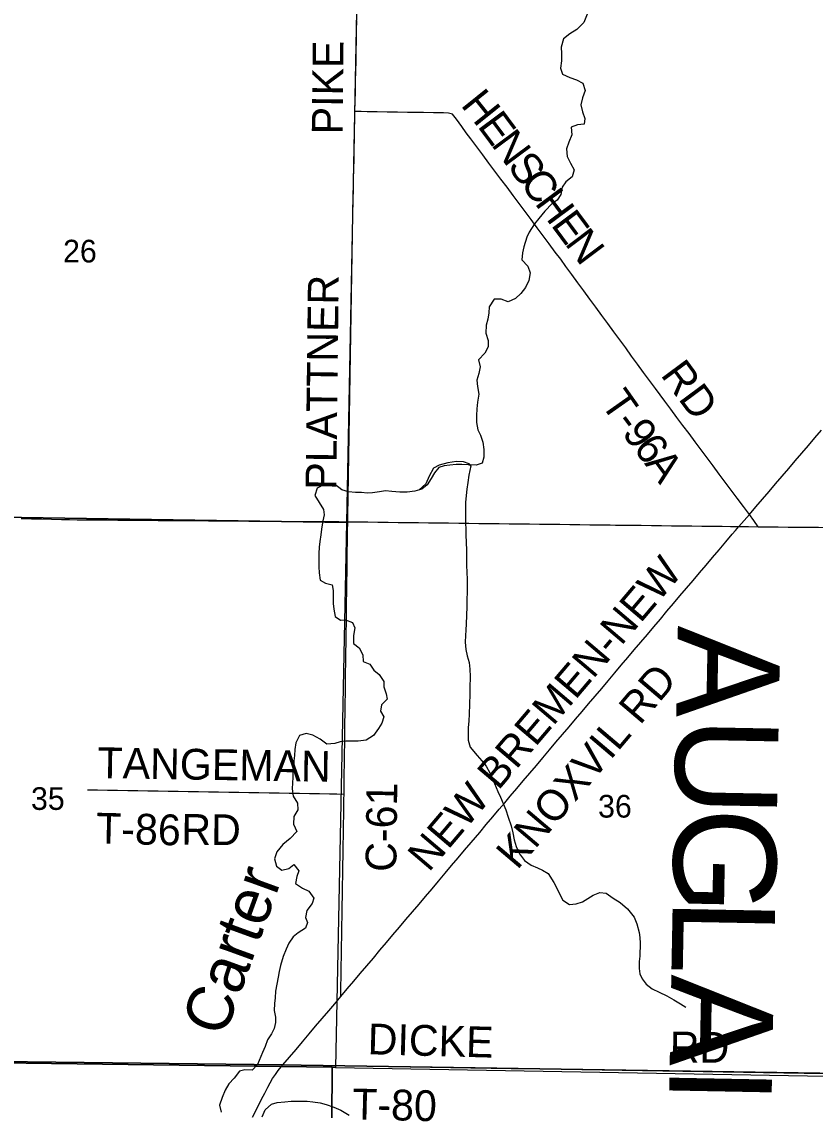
# Model space of a CAD drawing. Extents: x -11.1 to 34, y -3.9 to 22.
# Drawn here: x 5.806 to 7.271, y 18.172 to 20.181 of the extents above; entities that cross this region are included whole.
import ezdxf

# ---------------------------------------------------------------- set-up
doc = ezdxf.new("R2010")
doc.units = 0
for name, color, linetype in [('GM_X_Corporation', 7, 'Continuous'), ('GM_X_County_Road', 7, 'Continuous'), ('GM_X_County_Road_Text', 7, 'Continuous'), ('GM_X_County_Text', 7, 'Continuous'), ('GM_X_Minor_River', 7, 'Continuous'), ('GM_X_Minor_River_Text', 7, 'Continuous'), ('GM_X_Section_Text', 7, 'Continuous'), ('GM_X_Township_Road', 7, 'Continuous'), ('GM_X_Township_Road_Text', 7, 'Continuous')]:
    doc.layers.add(name, color=color, linetype=linetype)

msp = doc.modelspace()

# ---------------------------------------------------------------- linework, layer by layer
at = {"layer": 'GM_X_Corporation'}
for points in [[(7.452, 20.9), (2.1, 20.9), (2.1, 18.3243), (2.3663, 18.3195), (2.386, 18.3192), (3.3765, 18.301), (3.3885, 18.301), (4.3933, 18.2849), (4.8079, 18.2783), (5.3973, 18.2661), (6.2873, 18.2553), (6.3214, 18.2549), (6.5234, 18.2515), (7.399, 18.2383)], [(7.399, 18.2383), (6.5234, 18.2515), (6.3214, 18.2549), (6.2873, 18.2553), (5.3973, 18.2661), (4.8079, 18.2783), (4.3933, 18.2849), (3.3885, 18.301), (3.3765, 18.301), (2.386, 18.3192), (2.3663, 18.3195), (2.1, 18.3243), (2.1, 15.3106)]]:
    msp.add_lwpolyline(points, dxfattribs=at)
for points in [[(5.4232, 20.283), (6.4249, 20.2637), (6.4054, 19.2568), (5.4044, 19.2723)], [(5.4044, 19.2723), (6.4054, 19.2568), (6.3851, 18.2506), (6.3791, 18.2511), (5.3892, 18.2641)], [(5.3892, 18.2641), (6.3791, 18.2511), (6.3727, 17.2765), (5.385, 17.2762)], [(6.3851, 18.2506), (7.3955, 18.2326), (7.3797, 17.2828), (7.3791, 17.2313), (6.3727, 17.2765), (6.3791, 18.2511)]]:
    msp.add_lwpolyline(points, close=True, dxfattribs=at)
at = {"layer": 'GM_X_County_Road'}
for points in [[(6.3947, 18.3814), (6.395, 18.4), (6.3953, 18.4187), (6.3956, 18.4373), (6.3959, 18.4559), (6.3962, 18.4746), (6.3965, 18.4932), (6.3968, 18.5119), (6.3971, 18.5305), (6.3974, 18.5491), (6.3977, 18.5678), (6.398, 18.5864), (6.3983, 18.6051), (6.3986, 18.6237), (6.3989, 18.6424), (6.3992, 18.661), (6.3995, 18.6796), (6.3998, 18.6983), (6.4001, 18.7169), (6.4004, 18.7356), (6.4006, 18.7455), (6.4007, 18.7554), (6.401, 18.7741), (6.4012, 18.7927), (6.4015, 18.8114), (6.4017, 18.83), (6.402, 18.8486), (6.4022, 18.8673), (6.4025, 18.8859), (6.4027, 18.9046), (6.403, 18.9232), (6.4032, 18.9419), (6.4035, 18.9605), (6.4037, 18.9791), (6.404, 18.9978), (6.4042, 19.0164), (6.4045, 19.0351), (6.4048, 19.0537), (6.405, 19.0723), (6.4053, 19.091), (6.4055, 19.1096), (6.4058, 19.1283), (6.406, 19.1469), (6.4063, 19.1655), (6.4065, 19.1842), (6.4068, 19.2028), (6.407, 19.2215), (6.4073, 19.2398), (6.4075, 19.2581), (6.4078, 19.2768), (6.4081, 19.2954), (6.4084, 19.3141), (6.4088, 19.3327), (6.4091, 19.3514), (6.4094, 19.37), (6.4097, 19.3886), (6.41, 19.4073), (6.4103, 19.4259), (6.4106, 19.4446), (6.4109, 19.4632), (6.4112, 19.4818), (6.4115, 19.5005), (6.4119, 19.5191), (6.4122, 19.5378), (6.4125, 19.5564), (6.4128, 19.575), (6.4131, 19.5937), (6.4134, 19.6123), (6.4137, 19.631), (6.414, 19.6496), (6.4143, 19.6683), (6.4146, 19.6869), (6.4149, 19.7055), (6.4152, 19.7242), (6.4155, 19.7422), (6.4158, 19.7602), (6.4162, 19.7789), (6.4166, 19.7975), (6.417, 19.8161), (6.4173, 19.8348), (6.4177, 19.8534), (6.4181, 19.872), (6.4185, 19.8907), (6.4188, 19.9093), (6.4192, 19.928), (6.4196, 19.9466), (6.42, 19.9652), (6.4203, 19.9839), (6.4207, 19.9998), (6.421, 20.0158), (6.4214, 20.0344), (6.4218, 20.053), (6.4221, 20.0717), (6.4225, 20.0903), (6.4229, 20.1089), (6.4233, 20.1276), (6.4236, 20.1462), (6.424, 20.1649), (6.4244, 20.1835)], [(6.288, 18.2555), (6.3, 18.2697), (6.3121, 18.2839), (6.3241, 18.2981), (6.3362, 18.3124), (6.3483, 18.3266), (6.3603, 18.3408), (6.3724, 18.355), (6.3835, 18.3682), (6.3947, 18.3814), (6.4067, 18.3956), (6.4188, 18.4098), (6.4308, 18.4241), (6.4429, 18.4383), (6.4549, 18.4525), (6.4669, 18.4668), (6.479, 18.481), (6.491, 18.4952), (6.5031, 18.5094), (6.5151, 18.5237), (6.5272, 18.5379), (6.5392, 18.5521), (6.5512, 18.5664), (6.5633, 18.5806), (6.5753, 18.5948), (6.5873, 18.609), (6.5994, 18.6233), (6.6114, 18.6375), (6.6235, 18.6517), (6.6355, 18.666), (6.6434, 18.6753), (6.6513, 18.6846), (6.6633, 18.6989), (6.6753, 18.7131), (6.6874, 18.7273), (6.6976, 18.7394), (6.7077, 18.7514), (6.7198, 18.7656), (6.7318, 18.7798), (6.7439, 18.7941), (6.7559, 18.8083), (6.768, 18.8225), (6.78, 18.8367), (6.7921, 18.851), (6.8041, 18.8652), (6.8162, 18.8794), (6.8282, 18.8936), (6.8403, 18.9078), (6.8523, 18.9221), (6.8644, 18.9363), (6.8765, 18.9505), (6.8885, 18.9647), (6.9006, 18.979), (6.9126, 18.9932), (6.9247, 19.0074), (6.9367, 19.0216), (6.9488, 19.0359), (6.9608, 19.0501), (6.9729, 19.0643), (6.9849, 19.0785), (6.997, 19.0928), (7.009, 19.107), (7.0211, 19.1212), (7.0331, 19.1354), (7.0452, 19.1496), (7.0572, 19.1639), (7.0693, 19.1781), (7.0813, 19.1923), (7.0934, 19.2065), (7.1055, 19.2208), (7.1175, 19.235), (7.1236, 19.2422), (7.1297, 19.2494), (7.1395, 19.2605), (7.1492, 19.2715), (7.1613, 19.2857), (7.1735, 19.2999), (7.1856, 19.3141), (7.1977, 19.3282), (7.2098, 19.3424), (7.2219, 19.3566), (7.234, 19.3708), (7.2461, 19.3849), (7.2582, 19.3991), (7.2703, 19.4133), (7.2824, 19.4275)], [(6.2316, 18.1586), (6.2401, 18.1752), (6.2485, 18.1918), (6.2542, 18.2029), (6.2599, 18.2141), (6.2642, 18.2222), (6.2689, 18.23), (6.274, 18.2377), (6.2794, 18.2451), (6.288, 18.2555)]]:
    msp.add_lwpolyline(points, dxfattribs=at)
at = {"layer": 'GM_X_Minor_River'}
for points in [[(6.8495, 20.1956), (6.8438, 20.1802), (6.8305, 20.1669), (6.8174, 20.1593), (6.8061, 20.1497), (6.8019, 20.1346), (6.802, 20.1225), (6.8024, 20.1092), (6.8005, 20.0959), (6.8044, 20.0848), (6.8175, 20.0784), (6.8299, 20.0743), (6.8419, 20.0679), (6.8461, 20.0545), (6.8412, 20.041), (6.8382, 20.0278), (6.8413, 20.0148), (6.8455, 20.0029), (6.8441, 19.992), (6.8319, 19.9908), (6.8204, 19.9869), (6.8212, 19.9728), (6.8159, 19.9589), (6.8114, 19.9469), (6.8129, 19.9328), (6.819, 19.9201), (6.8255, 19.9078), (6.8222, 19.895), (6.8102, 19.8858), (6.8038, 19.8761), (6.8012, 19.8625), (6.7945, 19.8517), (6.7848, 19.8455), (6.7715, 19.8314), (6.7606, 19.8181), (6.7527, 19.8084), (6.7428, 19.7931), (6.738, 19.7834), (6.7326, 19.766), (6.7301, 19.7547), (6.7293, 19.7415), (6.74, 19.7298), (6.7446, 19.7179), (6.742, 19.7036), (6.7356, 19.6908), (6.7273, 19.6797), (6.7176, 19.6701), (6.7038, 19.6643), (6.691, 19.6692), (6.6777, 19.6692), (6.669, 19.655), (6.6683, 19.644), (6.6661, 19.6323), (6.6632, 19.621), (6.6628, 19.6066), (6.6666, 19.5928), (6.667, 19.5814), (6.661, 19.5695), (6.6489, 19.5569), (6.652, 19.5439), (6.6498, 19.5318), (6.6461, 19.5198), (6.6469, 19.5076), (6.6499, 19.4935)], [(6.6499, 19.4935), (6.6469, 19.4787), (6.6462, 19.4666), (6.6455, 19.4541), (6.6455, 19.4412), (6.6478, 19.4279), (6.6525, 19.4179), (6.6571, 19.4049), (6.6586, 19.3915), (6.6586, 19.3775), (6.656, 19.3666), (6.6449, 19.3627), (6.6302, 19.3634), (6.6184, 19.3641), (6.6078, 19.3637), (6.596, 19.3628), (6.5857, 19.3612), (6.5758, 19.358), (6.5675, 19.3484), (6.5616, 19.3383), (6.554, 19.326), (6.5444, 19.3186), (6.5314, 19.3144), (6.5173, 19.3125), (6.5036, 19.3129), (6.4892, 19.314), (6.4771, 19.3151), (6.4661, 19.3135), (6.4535, 19.3115), (6.4436, 19.311), (6.433, 19.3121), (6.4217, 19.3124), (6.4088, 19.3134), (6.3964, 19.3172), (6.3834, 19.3278), (6.3735, 19.3288), (6.364, 19.3271), (6.3509, 19.3199), (6.3468, 19.3067), (6.3551, 19.2936), (6.3631, 19.2805), (6.364, 19.2706), (6.3618, 19.2597), (6.3591, 19.2442), (6.3577, 19.234), (6.3563, 19.2218), (6.3549, 19.2109), (6.3542, 19.1995), (6.3542, 19.1859), (6.3543, 19.1748), (6.3551, 19.1638), (6.3567, 19.1505), (6.3668, 19.1449), (6.3788, 19.1416), (6.3808, 19.1309), (6.3805, 19.1184), (6.3809, 19.1074), (6.3822, 19.0967), (6.3841, 19.0834), (6.3942, 19.0767), (6.4037, 19.0772), (6.4161, 19.0723), (6.4207, 19.0623), (6.4181, 19.0483), (6.4184, 19.0331), (6.4285, 19.0253), (6.4353, 19.0126), (6.4362, 19), (6.4482, 18.9952), (6.4558, 18.984), (6.4655, 18.9761), (6.4742, 18.963), (6.474, 18.9535), (6.4786, 18.9401), (6.4802, 18.9306), (6.4697, 18.9199), (6.4682, 18.9081), (6.474, 18.8981), (6.4707, 18.8864), (6.4647, 18.8763), (6.4549, 18.8637), (6.4418, 18.8549), (6.4269, 18.8531), (6.4167, 18.8529), (6.4038, 18.8533), (6.3939, 18.852), (6.3836, 18.8489), (6.3691, 18.8477), (6.3569, 18.8568), (6.343, 18.8643), (6.3306, 18.867), (6.3187, 18.8635), (6.3119, 18.85), (6.3101, 18.8375), (6.309, 18.8265), (6.308, 18.8167), (6.3073, 18.8065), (6.3063, 18.7955), (6.306, 18.786), (6.3054, 18.7758), (6.3051, 18.7648)], [(6.6349, 19.3613), (6.6317, 19.3653), (6.6216, 19.3686), (6.6083, 19.3693), (6.5927, 19.3671), (6.5766, 19.3629), (6.5659, 19.3572), (6.5579, 19.3422), (6.5515, 19.3283), (6.5394, 19.3172)], [(6.6349, 19.3613), (6.6312, 19.3444), (6.6293, 19.3308), (6.6274, 19.318), (6.626, 19.3063), (6.6253, 19.2938), (6.6249, 19.2801), (6.625, 19.2672), (6.625, 19.2554), (6.6255, 19.2444), (6.6256, 19.2342), (6.626, 19.2197), (6.6267, 19.2057), (6.6268, 19.1928), (6.6271, 19.1772), (6.6276, 19.165), (6.6283, 19.1517), (6.6284, 19.1388), (6.6281, 19.1286), (6.6273, 19.1138), (6.6274, 19.1013), (6.6265, 19.0694), (6.6259, 19.0577), (6.6252, 19.0482), (6.6245, 19.0361), (6.6257, 19.0224), (6.6284, 19.0106), (6.6319, 18.9983), (6.6331, 18.9862), (6.6335, 18.9725), (6.6329, 18.9513), (6.633, 18.9399), (6.632, 18.9031), (6.6313, 18.8906), (6.6302, 18.8777), (6.6299, 18.8671), (6.63, 18.8546), (6.6334, 18.842), (6.6463, 18.8268), (6.6551, 18.8167), (6.6629, 18.807), (6.6701, 18.7947), (6.6748, 18.7847), (6.6787, 18.7751), (6.6848, 18.7602), (6.6898, 18.7498), (6.6948, 18.7379), (6.6994, 18.726), (6.704, 18.7126), (6.7093, 18.6969), (6.7123, 18.6839), (6.715, 18.6706), (6.7185, 18.6583), (6.7246, 18.6449), (6.7341, 18.6325), (6.746, 18.6239), (6.7577, 18.619), (6.7674, 18.6149), (6.7779, 18.6086), (6.7881, 18.592), (6.7949, 18.5793), (6.7992, 18.5697), (6.8046, 18.5593), (6.8169, 18.5514), (6.8291, 18.5526), (6.841, 18.5561), (6.851, 18.5623), (6.861, 18.5689), (6.8729, 18.5735), (6.8847, 18.5724), (6.8977, 18.5633), (6.9104, 18.555), (6.9241, 18.5437), (6.9362, 18.5282), (6.9412, 18.5159), (6.9457, 18.4999), (6.947, 18.4903), (6.9475, 18.4801), (6.9468, 18.4558), (6.9458, 18.446), (6.9455, 18.4331), (6.9471, 18.4235), (6.951, 18.414), (6.9587, 18.4043), (6.9699, 18.3956), (6.9826, 18.3896), (6.9969, 18.3828), (7.01, 18.3756), (7.0223, 18.3681), (7.032, 18.3621)], [(6.3051, 18.7648), (6.3066, 18.7515), (6.3146, 18.7383), (6.3155, 18.7262), (6.3079, 18.7139), (6.3076, 18.6998), (6.3137, 18.6864), (6.3012, 18.6731), (6.2876, 18.6624), (6.2766, 18.6486), (6.2725, 18.6359), (6.2759, 18.6225), (6.2856, 18.6146), (6.2986, 18.6177), (6.3082, 18.6254), (6.317, 18.6134), (6.3134, 18.6033), (6.3111, 18.5904), (6.3238, 18.5814), (6.3358, 18.5761), (6.3449, 18.5634), (6.342, 18.5532), (6.3322, 18.5402), (6.3296, 18.5277), (6.3335, 18.5181), (6.3298, 18.508), (6.3163, 18.4992), (6.3066, 18.4919), (6.2991, 18.4799), (6.2939, 18.4691), (6.2886, 18.4556), (6.2832, 18.4386), (6.281, 18.4277), (6.2792, 18.4171), (6.2766, 18.4043), (6.2744, 18.3914), (6.2733, 18.3793), (6.2722, 18.3687), (6.2719, 18.3558), (6.2742, 18.3432), (6.2743, 18.3334), (6.2718, 18.3224), (6.2666, 18.3127), (6.2595, 18.3015), (6.255, 18.2895), (6.2505, 18.2782), (6.2408, 18.2557), (6.2314, 18.2457), (6.2178, 18.246), (6.2079, 18.2436), (6.198, 18.231), (6.1879, 18.2202), (6.1811, 18.2083), (6.1755, 18.1948), (6.1709, 18.1812), (6.174, 18.1682)], [(6.2496, 18.1594), (6.2553, 18.1722), (6.267, 18.1829), (6.2773, 18.186), (6.2917, 18.1872), (6.3031, 18.1884), (6.3126, 18.1885), (6.3327, 18.188), (6.3429, 18.1873), (6.3569, 18.1855), (6.3675, 18.1822), (6.3818, 18.1772), (6.3949, 18.1716), (6.4102, 18.1624)]]:
    msp.add_lwpolyline(points, dxfattribs=at)
at = {"layer": 'GM_X_Township_Road'}
for points in [[(7.1652, 19.249), (7.1572, 19.2602), (7.1492, 19.2715), (7.1381, 19.2865), (7.1269, 19.3014), (7.1158, 19.3164), (7.1046, 19.3313), (7.0935, 19.3463), (7.0823, 19.3612), (7.0712, 19.3762), (7.0601, 19.3911), (7.0489, 19.406), (7.0378, 19.421), (7.0266, 19.4359), (7.0155, 19.4509), (7.0043, 19.4658), (6.9932, 19.4808), (6.9846, 19.4923), (6.9759, 19.5039), (6.9649, 19.5189), (6.9539, 19.5339), (6.9429, 19.549), (6.9318, 19.564), (6.9208, 19.579), (6.9098, 19.5941), (6.8988, 19.6091), (6.8878, 19.6242), (6.8767, 19.6392), (6.8657, 19.6542), (6.8547, 19.6693), (6.8437, 19.6843), (6.8326, 19.6993), (6.8216, 19.7144), (6.8106, 19.7294), (6.8008, 19.7428), (6.7909, 19.7562), (6.7798, 19.7712), (6.7686, 19.7861), (6.7575, 19.8011), (6.7463, 19.816), (6.7352, 19.8309), (6.724, 19.8459), (6.7128, 19.8608), (6.7017, 19.8757), (6.6905, 19.8907), (6.6794, 19.9056), (6.6682, 19.9205), (6.6571, 19.9355), (6.6459, 19.9504), (6.6348, 19.9653), (6.6264, 19.9765), (6.618, 19.9877), (6.6085, 20.0013), (6.601, 20.0105), (6.5935, 20.0127), (6.5846, 20.0131), (6.5659, 20.0133), (6.5473, 20.0135), (6.5326, 20.0137), (6.518, 20.0139), (6.4993, 20.0142), (6.4807, 20.0146), (6.4621, 20.015), (6.4434, 20.0153), (6.4322, 20.0156), (6.421, 20.0158)], [(5.8048, 19.2642), (5.8234, 19.2638), (5.8421, 19.2633), (5.8607, 19.2629), (5.8793, 19.2625), (5.8938, 19.2621), (5.9082, 19.2618), (5.9269, 19.2617), (5.9455, 19.2615), (5.9641, 19.2614), (5.9828, 19.2613), (6.0014, 19.2611), (6.0201, 19.261), (6.0387, 19.2609), (6.0574, 19.2607), (6.076, 19.2606), (6.0946, 19.2604), (6.1133, 19.2603), (6.1319, 19.2602), (6.1506, 19.26), (6.1692, 19.2599), (6.1878, 19.2598), (6.2065, 19.2596), (6.2251, 19.2595), (6.2438, 19.2594), (6.2624, 19.2592), (6.281, 19.2591), (6.2997, 19.2589), (6.3183, 19.2588), (6.337, 19.2587), (6.3556, 19.2585), (6.3743, 19.2584), (6.3909, 19.2583), (6.4075, 19.2581), (6.4262, 19.2579), (6.4448, 19.2577), (6.4634, 19.2575), (6.4821, 19.2572), (6.5007, 19.257), (6.5194, 19.2568), (6.538, 19.2566), (6.5566, 19.2563), (6.5753, 19.2561), (6.5939, 19.2559), (6.6126, 19.2557), (6.6312, 19.2554), (6.6498, 19.2552), (6.6685, 19.255), (6.6871, 19.2548), (6.7058, 19.2545), (6.7244, 19.2543), (6.743, 19.2541), (6.7617, 19.2538), (6.7803, 19.2536), (6.799, 19.2534), (6.8176, 19.2532), (6.8363, 19.2529), (6.8549, 19.2527), (6.8735, 19.2525), (6.8922, 19.2523), (6.9022, 19.2521), (6.9123, 19.252), (6.9309, 19.2518), (6.9496, 19.2516), (6.9682, 19.2513), (6.9869, 19.2511), (7.0055, 19.2509), (7.0241, 19.2507), (7.0428, 19.2504), (7.0614, 19.2502), (7.0801, 19.25), (7.0987, 19.2498), (7.1142, 19.2496), (7.1297, 19.2494)], [(7.1297, 19.2494), (7.1475, 19.2492), (7.1652, 19.249), (7.1839, 19.2488), (7.2025, 19.2486), (7.2211, 19.2484), (7.2398, 19.2482), (7.2584, 19.2481), (7.2771, 19.2479), (7.2957, 19.2477), (7.3143, 19.2475), (7.333, 19.2473), (7.3516, 19.2472), (7.3703, 19.247), (7.3889, 19.2468), (7.4037, 19.2467), (7.4184, 19.2465)], [(5.9268, 18.7634), (5.9455, 18.7631), (5.9641, 18.7628), (5.9827, 18.7624), (6.0014, 18.7621), (6.02, 18.7618), (6.0387, 18.7615), (6.0573, 18.7612), (6.0759, 18.7609), (6.0946, 18.7606), (6.1132, 18.7603), (6.1319, 18.76), (6.1505, 18.7596), (6.1692, 18.7593), (6.1878, 18.759), (6.2064, 18.7587), (6.2251, 18.7584), (6.2437, 18.7581), (6.2624, 18.7578), (6.2769, 18.7575)], [(6.2769, 18.7575), (6.281, 18.7575), (6.2996, 18.7571), (6.3183, 18.7568), (6.3369, 18.7565), (6.3556, 18.7562), (6.3742, 18.7559), (6.3875, 18.7557), (6.4007, 18.7554)], [(6.288, 18.2555), (6.3066, 18.2552), (6.3253, 18.255), (6.3439, 18.2547), (6.3625, 18.2545), (6.3776, 18.2542), (6.3927, 18.254), (6.4113, 18.2537), (6.4299, 18.2534), (6.4486, 18.2531), (6.4672, 18.2528), (6.4859, 18.2525), (6.5045, 18.2522), (6.5231, 18.2519), (6.5418, 18.2516), (6.5604, 18.2513), (6.5791, 18.251), (6.5977, 18.2507), (6.6163, 18.2504), (6.635, 18.2501), (6.6536, 18.2498), (6.6723, 18.2495), (6.6909, 18.2492), (6.7096, 18.2489), (6.7282, 18.2486), (6.7468, 18.2483), (6.7655, 18.248), (6.7841, 18.2477), (6.8028, 18.2474), (6.8214, 18.2471), (6.84, 18.2468), (6.8587, 18.2465), (6.8773, 18.2462), (6.896, 18.2459), (6.9146, 18.2456), (6.9332, 18.2453), (6.9519, 18.245), (6.9705, 18.2447), (6.9892, 18.2444), (7.0078, 18.2441), (7.0265, 18.2438), (7.0451, 18.2435), (7.0637, 18.2432), (7.0824, 18.2429), (7.101, 18.2426), (7.1197, 18.2423), (7.1383, 18.242), (7.1569, 18.2417), (7.1756, 18.2414), (7.1942, 18.2411), (7.2129, 18.2408), (7.2315, 18.2405), (7.2501, 18.2402), (7.2688, 18.2399), (7.2874, 18.2396)]]:
    msp.add_lwpolyline(points, dxfattribs=at)

# ---------------------------------------------------------------- texts
at = {"layer": 'GM_X_County_Road_Text'}
for s, height, rotation, p in [('PIKE', 0.05682, 89.393, (6.398, 19.9731)), ('PLATTNER', 0.05682, 89.3277, (6.3864, 19.3169)), ('NEW BREMEN-NEW', 0.056818, 49.6467, (6.5573, 18.6096)), ('KNOXVIL RD', 0.05682, 49.7166, (6.7206, 18.6139)), ('C-61', 0.05682, 89.3136, (6.4972, 18.6115))]:
    msp.add_text(s, height=height, rotation=rotation, dxfattribs=at).set_placement(p)
at = {"layer": 'GM_X_County_Text'}
for s, rotation, p in [('A', 268.931, (7.0172, 19.0666)), ('U', 268.9294, (7.0141, 18.8992)), ('G', 268.9267, (7.011, 18.7317)), ('L', 268.9212, (7.0078, 18.5642)), ('A', 268.9071, (7.0052, 18.4226)), ('I', 268.8989, (7.002, 18.2551))]:
    msp.add_text(s, height=0.1894, rotation=rotation, dxfattribs=at).set_placement(p)
at = {"layer": 'GM_X_Minor_River_Text'}
msp.add_text('Carter', height=0.08523, rotation=70.026, dxfattribs=at).set_placement((6.1794, 18.3043))
at = {"layer": 'GM_X_Section_Text'}
for s, p in [('26', (5.8819, 19.7369)), ('35', (5.8227, 18.7261)), ('36', (6.8698, 18.7119))]:
    msp.add_text(s, height=0.04186, rotation=0, dxfattribs=at).set_placement(p)
at = {"layer": 'GM_X_Township_Road_Text'}
for s, height, rotation, p in [('H', 0.0568, 308.8072, (6.6149, 20.0272)), ('E', 0.0568, 306.6398, (6.6459, 19.9887)), ('N', 0.0568, 306.6011, (6.6713, 19.9546)), ('S', 0.0568, 306.6037, (6.7011, 19.9144)), ('C', 0.0568, 306.6022, (6.7239, 19.8837)), ('H', 0.0568, 306.6014, (6.7517, 19.8462)), ('E', 0.0568, 306.6051, (6.7816, 19.8061)), ('N', 0.0568, 306.9314, (6.8071, 19.7717)), ('RD', 0.05682, 306.573, (6.984, 19.5293)), ('T', 0.0568, 305.1082, (6.8733, 19.4768)), ('-', 0.0568, 306.4247, (6.8986, 19.4409)), ('9', 0.0568, 306.6469, (6.9126, 19.4219)), ('6', 0.0568, 306.731, (6.9335, 19.3938)), ('A', 0.0568, 306.751, (6.9544, 19.3657)), ('TANGEMAN', 0.05682, 359.041, (5.9452, 18.785)), ('T-86', 0.05682, 358.6533, (5.9425, 18.6641)), ('RD', 0.05682, 359.5064, (6.1002, 18.6617)), ('DICKE', 0.05682, 358.4279, (6.4439, 18.275)), ('RD', 0.05682, 359.5064, (7.002, 18.26)), ('T-80', 0.05682, 358.6026, (6.4153, 18.1549))]:
    msp.add_text(s, height=height, rotation=rotation, dxfattribs=at).set_placement(p)

doc.saveas('drawing.dxf')
